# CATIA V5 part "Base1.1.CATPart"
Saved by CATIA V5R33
Part number: Base1.1
Property "V_IsManufacturable": "true"
Property "V_Scale": "NormalScale"
Property "V_isTerminal": "true"
Property "V_ChangeHistory": "false"
Property "V_isLastVersion": "true"
Property "V_isVPLMControlled": "true"
Property "V_AuthorityControl": "false"
Property "V_ProjectApplicability": "List"
Property "V_Name": "Base"
Property "PLM_ExternalID": "prd00000094"
Property "V_usage": "3DPart"
Property "V_nature": "Definition"
Property "V_sec_level": "-1"
Property "owner": "admin_platform"
Property "project": "New Space 1"
Property "organization": "Company Name"
Property "revision": "1.1"
Property "originated": "03/13/2024 :: 02:56:00 PM"
Property "modified": "03/13/2024 :: 02:58:40 PM"
Property "reserved": "true"
Property "reservedby": "admin_platform"
Property "current": "IN_WORK"
Property "name": "prd00000094"
Property "locked": "false"
Property "revindex": "0"
Property "isbestsofar": "true"
Property "minorrevision": "1"
Property "majorrevision": "1"
Property "ispublished": "false"
Property "policy": "VPLM_SMB_Definition"
Bounding box of the stored display mesh (mm): x -37.5 to 37.5, y 0 to 300, z -15 to 0
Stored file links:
  C:\Users\Chris Brodowski\Documents\3D Objects\Export\Base1.1.CATPart

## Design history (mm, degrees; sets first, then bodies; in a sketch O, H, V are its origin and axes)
Parameters
  Length_base = 300 mm
  width_base = 75 mm
MechanicalRefPlane1 "xy-plane"
MechanicalRefPlane2 "yz-plane"
MechanicalRefPlane3 "zx-plane"
AxisSystem1: origin (0, 0, 0), X (1, 0, 0), Y (0, 1, 0), Z (0, 0, 1)
Body1 (main body)
  Sketch1 on XY plane of AxisSystem1, origin (0, 0, 0), H (0, 1, 0), V (-1, 0, 0)
    line L1 (0, 37.5) -> (300, 37.5)
    line L2 (300, 37.5) -> (300, -37.5)
    line L3 (300, -37.5) -> (0, -37.5)
    line L4 (0, -37.5) -> (0, 37.5)
    line L5 (127, 23.404) -> (152, 23.404)
    line L6 (152, 23.404) -> (152, -6.596)
    line L7 (152, -6.596) -> (127, -6.596)
    line L8 (127, -6.596) -> (127, 23.404)
    "Length" L3 = 300 {= Length_base}
    "Length" L2 = 75 {= width_base}
    "Offset" L1 H = 37.5 {= width_base/2}
    "Offset" L8 V = 127
    "Length" L8 = 30
    "Length" L7 = 25
  Pad1: profile Sketch1, direction (0, 0, -1), length 15, opposite side length -1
